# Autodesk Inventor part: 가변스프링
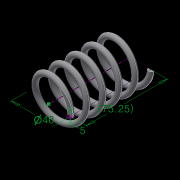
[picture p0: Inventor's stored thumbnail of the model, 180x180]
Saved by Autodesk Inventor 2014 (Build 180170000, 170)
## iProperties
Created: 2018-04
Part Number: 가변스프링
Material: 스테인레스 스틸
Document SubType Name: Modeling
Designer: 703
Density: 1 g/cm^3
Appearance: 반연마
Author: 703
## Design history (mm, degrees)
sketch "스케치1"
  geometry: L1 (0, 0)-(20, 0); L2 (20, 0)-(20, 75.25); L3 (20, 75.25)-(0, 75.25); L4 (0, 75.25)-(0, 0); C1 r 2.5 at (20, 0); 1 further point
  constraints: 8 end point, 2 coincident, 2 parallel, 1 centre point, 1 horizontal, 1 perpendicular
  dimensions: "d1" = 40 diameter of L2 L4; "d2" = 75.25 distance of L1.end L2.end (derived); "d3" = 5 diameter of C1
feature "코일1" sketch "스케치1" pitch "d4" = 10; turns "d6" = 5; dims "d5" = 75.25 (= d2), "d7" = 0, angle "d8" = 90 deg, angle "d9" = 90 deg, "d10" = 0, "d11" = 0
sketch "스케치2"
  geometry: L1 (-17.5, 0)-(-22.5, 0) reference; 1 further point
  constraints: 1 horizontal alignment
extrude "돌출1" cut sketch "스케치2" distance "d12" = 10; taper "d13" = 0 deg
node "작업 평면1"
sketch "스케치3"
  geometry: L1 (-22.5, 0)-(-17.5, 0) reference; 1 further point
  constraints: 1 horizontal alignment
extrude "돌출2" cut sketch "스케치3" distance "d14" = 10; taper "d15" = 0 deg
node "솔리드1"
node "절단 모서리 투영1"
node "절단 모서리 투영2"
